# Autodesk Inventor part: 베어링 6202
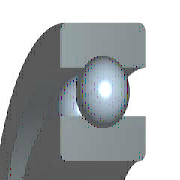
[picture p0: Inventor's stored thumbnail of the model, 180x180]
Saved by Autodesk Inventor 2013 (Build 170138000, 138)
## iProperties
Created: 2009-02
Part Number: 베어링 6202
Material: 강, 연강
Description: 깊은 그루브 볼 베어링
Document SubType Name: Modeling
Standard: KS B 2023
Designer: KYOUNG IL JANG
Standards Organization: KS
Language: ko-KR
Size Designation: 6202 - 15 x 35 x 11
Categories: <MemberInstance><Categories><Category DisplayName="샤프트 부품" InternalName="7f7aeb1f-a693-4053-b835-cee3144e0d98" Mnemonic="SHFT"><Category DisplayName="베어링" Inter
Density: 7.86 g/cm^3
Mass: 45.8725 g
Surface Area: 51.5584 cm^2
Volume: 5.83619 cm^3
Vendor: CBT Solutions
Company: 한국ATC센터
IsCustomPart: 1
Author: KYOUNG IL JANG
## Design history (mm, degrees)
sketch "스케치" dims "d0" = 5.2 (= -0.26 x WD + 0.26 x BD)
  geometry: L1 (2.9, 12.5)-(8.1, 12.5); L2 (5.5, 12.5)-(5.5, 9.9); L3 (5.5, 12.5)-(5.5, 15.1); L4 (3.568, 10.76)-(0, 10.76); L5 (0, 7.5)-(11, 7.5); L6 (3.568, 14.24)-(0, 14.24); L7 (0, 17.5)-(11, 17.5); L8 (11, 7.5)-(11, 10.76); L9 (7.432, 10.76)-(11, 10.76); L10 (7.432, 14.24)-(11, 14.24); L11 (11, 17.5)-(11, 14.24); L12 (-1.4, 0)-(8.4, 0) reference; L13 (0, -0.3)-(0, 5.3) reference
  constraints: 22 end point, 4 point on line, 2 collinear, 2 perpendicular, 2 symmetric about line, 1 midpoint, 1 parallel, 14 other
  dimensions: "d9" = 15 diameter of L5 L12 (= WD); "d11" = 35 diameter of L7 L12 (= BD); "d12" = 11 distance between parallel lines of L8 L13 (= KB); "d13" = 21.52 diameter of L9 L12 (= 0.326 x BD + 0.674 x WD)
revolve "본체" stored, may be unused: angle "d6" = 90 deg
revolve "볼" stored, may be unused: angle "d7" = 90 deg
pattern_circular "IDS_ARRAYBALL[SIMPL:T]" dims angle "d3" = 360 deg
body "Solid1"
fillet "모깎기1" dims "d1" = 0.6 (= KRS)
other parameters: "WD" = 15 [user parameter; used in 5 equation terms], "BD" = 35 [user parameter; used in 5 equation terms], "KB" = 11 [user parameter; used in 1 equation term], "KRS" = 0.6 [user parameter; used in 1 equation term], "d4" = 0, "d5" = 0, "d8" = 0, "d14" = 0, "d15" = 0, "BBA" = 0 [user parameter], "BC0" = 3750000 [user parameter], "BC" = 7800000 [user parameter], "BR" = 17.5 (= 0.5 x BD) [user parameter], "WR" = 7.5 (= 0.5 x WD) [user parameter]
